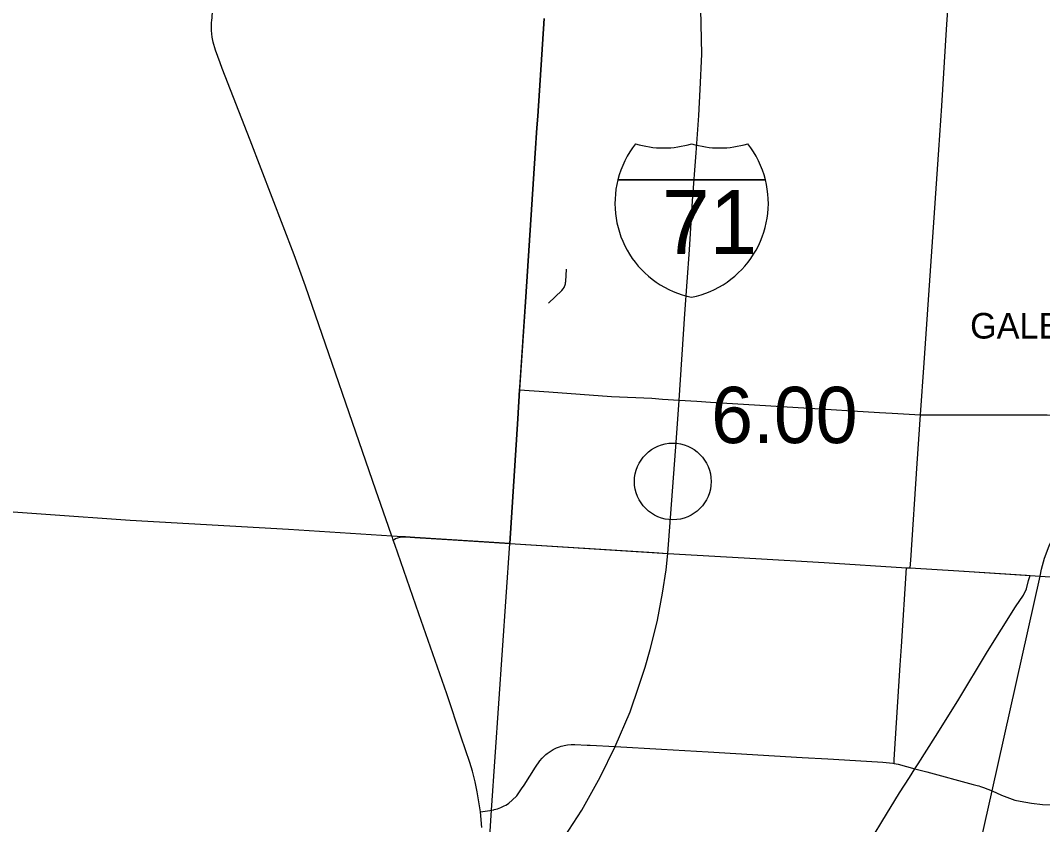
# Model space of a CAD drawing. Extents: x 1597222 to 1925846, y 496284 to 911751.
# Drawn here: x 1835573 to 1855559, y 799690 to 815408 of the extents above; entities that cross this region are included whole.
import ezdxf

# ---------------------------------------------------------------- set-up
doc = ezdxf.new("R2010")
doc.units = 0
for name, color, linetype in [('Default', 7, 'Continuous'), ('GM_X_Corporation_Text', 7, 'Continuous'), ('GM_X_County_Road', 7, 'Continuous'), ('GM_X_Interstate_Route', 7, 'Continuous'), ('GM_X_Interstate_Shield', 7, 'Continuous'), ('GM_X_State_Route', 7, 'Continuous'), ('GM_X_Township', 7, 'Continuous'), ('GM_X_Township_Road', 7, 'Continuous')]:
    doc.layers.add(name, color=color, linetype=linetype)

msp = doc.modelspace()

# ---------------------------------------------------------------- linework, layer by layer
at = {"layer": 'Default'}
msp.add_circle((1848329, 806396), 750, dxfattribs=at)
at = {"layer": 'GM_X_County_Road'}
for points in [[(1852972, 804706), (1852981, 804856), (1853110, 806745), (1853175, 807697), (1853246, 808714), (1853530, 812876), (1853592, 813742), (1853681, 815234), (1853705, 815613), (1853731, 815995), (1853772, 816725), (1853832, 817646), (1853875, 818312), (1853892, 818538)], [(1842846, 805301), (1842837, 805328), (1842772, 805518), (1842519, 806229), (1841146, 810217), (1840928, 810827), (1840065, 813066), (1839518, 814468), (1839479, 814577), (1839387, 814825), (1839342, 814985), (1839324, 815084), (1839310, 815214), (1839307, 815315), (1839311, 815371), (1839312, 815408), (1839319, 815463), (1839325, 815513), (1839372, 815780)], [(1844595, 799631), (1844566, 799941), (1844505, 800330), (1844464, 800522), (1844412, 800732), (1844363, 800904), (1844193, 801395), (1843910, 802243), (1843360, 803811), (1842894, 805162), (1842863, 805251), (1842846, 805301)], [(1852657, 800886), (1852657, 800961), (1852774, 802805), (1852798, 803172), (1852898, 804710), (1852972, 804706)], [(1844838, 799981), (1844901, 799998), (1844968, 800023), (1845033, 800054), (1845064, 800071), (1845094, 800091), (1845124, 800110), (1845190, 800164), (1845278, 800253), (1845373, 800385), (1845425, 800462), (1845644, 800809), (1845729, 800932), (1845773, 800986), (1845847, 801059), (1845874, 801080), (1845931, 801120), (1845991, 801156), (1846052, 801187), (1846116, 801212), (1846148, 801222), (1846234, 801241), (1846270, 801248), (1846343, 801255), (1846416, 801256), (1846655, 801244)], [(1846655, 801244), (1846713, 801241), (1847205, 801213), (1848107, 801161), (1849018, 801108), (1850858, 801002), (1851359, 800976), (1852118, 800926), (1852433, 800906), (1852629, 800889), (1852657, 800886), (1852736, 800868), (1853063, 800779), (1853297, 800719), (1854203, 800475), (1854282, 800454), (1854310, 800445)], [(1851239, 797854), (1851501, 798281), (1851653, 798524), (1851853, 798834), (1852115, 799249), (1852419, 799742), (1852763, 800311), (1852954, 800610), (1853063, 800779)], [(1854310, 800445), (1854348, 800433), (1854402, 800414), (1854573, 800349)], [(1854573, 800349), (1854755, 800266), (1854914, 800205), (1855015, 800169), (1855118, 800145), (1855340, 800109), (1855555, 800083), (1855746, 800073), (1856041, 800054), (1856308, 800043), (1856579, 800027), (1856677, 800021), (1856906, 800027), (1857196, 800056), (1857340, 800059), (1857473, 800073), (1857580, 800087), (1857682, 800095), (1857756, 800098), (1857798, 800096), (1857874, 800083), (1857988, 800064)], [(1844566, 799941), (1844753, 799964), (1844785, 799970), (1844828, 799978), (1844838, 799981)]]:
    msp.add_lwpolyline(points, dxfattribs=at)
at = {"layer": 'GM_X_Interstate_Route'}
msp.add_lwpolyline([(1846211, 799449), (1846552, 799972), (1846911, 800613), (1847205, 801213), (1847493, 801891), (1847666, 802395), (1847786, 802765), (1847888, 803110), (1847964, 803419), (1848028, 803685), (1848125, 804211), (1848200, 804670), (1848231, 804991), (1848401, 807248), (1848453, 807987), (1848565, 809674), (1848656, 810925), (1848716, 811884), (1848786, 812818), (1848839, 813548), (1848865, 814059), (1848894, 814749), (1848860, 816509)], dxfattribs=at)
at = {"layer": 'GM_X_Interstate_Shield'}
for p, q in [((1847254, 812294), (1850140, 812294)), ((1850140, 812294), (1847254, 812294)), ((1850140, 812294), (1847254, 812294)), ((1847254, 812294), (1850140, 812294)), ((1850140, 812294), (1847254, 812294)), ((1850140, 812294), (1847254, 812294))]:
    msp.add_line(p, q, dxfattribs=at)
for centre, start, end in [((1849072, 811835), 141.669, 165.8066), ((1849072, 811835), 141.669, 165.8066), ((1848149, 814791), 253.0091, 286.9909), ((1848149, 814791), 253.0091, 286.9909), ((1849245, 814791), 253.0091, 286.9909), ((1849245, 814791), 253.0091, 286.9909), ((1848322, 811835), 14.1934, 38.331), ((1848322, 811835), 14.1934, 38.331), ((1849072, 811835), 165.8066, 258.463), ((1849072, 811835), 165.8066, 258.463), ((1848322, 811835), 281.537, 14.1934), ((1848322, 811835), 281.537, 14.1934)]:
    msp.add_arc(centre, 1875, start, end, dxfattribs=at)
at = {"layer": 'GM_X_State_Route'}
msp.add_lwpolyline([(1853225, 794338), (1854573, 800349), (1855512, 804546), (1855541, 804679), (1855596, 804898), (1855689, 805139), (1855836, 805465), (1855908, 805599), (1856008, 805767), (1856148, 805978), (1856255, 806119), (1856504, 806413), (1857597, 807668), (1858467, 808668), (1858818, 809072), (1859440, 809788), (1860025, 810459)], dxfattribs=at)
at = {"layer": 'GM_X_Township'}
for points in [[(1845813, 815443), (1845687, 813540), (1845670, 813309), (1845637, 812811), (1845452, 810003), (1845333, 808188), (1845296, 807619), (1845145, 805182), (1843287, 805303), (1843103, 805315), (1843041, 805313), (1842837, 805328), (1840812, 805456), (1837716, 805633), (1832763, 805986)], [(1844685, 798421), (1844785, 799970), (1845145, 805182), (1848231, 804991), (1849953, 804892), (1851286, 804810), (1852898, 804710), (1852972, 804706), (1853920, 804647), (1855314, 804559), (1855512, 804546), (1855904, 804520)]]:
    msp.add_lwpolyline(points, dxfattribs=at)
at = {"layer": 'GM_X_Township_Road'}
for points in [[(1845336, 808240), (1845452, 810003), (1845637, 812811), (1845670, 813309), (1845687, 813540), (1845813, 815443)], [(1845901, 809883), (1846157, 810131), (1846187, 810162), (1846202, 810185), (1846214, 810206), (1846226, 810238), (1846229, 810261), (1846233, 810284), (1846236, 810308), (1846248, 810548)], [(1845145, 805182), (1845296, 807619), (1845333, 808188), (1845336, 808240)], [(1845333, 808188), (1845902, 808151), (1847128, 808058), (1847922, 808022), (1848130, 808008), (1848453, 807987), (1848798, 807964), (1849069, 807946), (1851423, 807800), (1851838, 807775), (1852372, 807742), (1852621, 807728), (1853175, 807697)], [(1853175, 807697), (1854218, 807699), (1855651, 807697), (1856991, 807682), (1857244, 807678), (1857423, 807675), (1857597, 807668)], [(1842863, 805251), (1842909, 805278), (1842951, 805293), (1842996, 805306), (1843041, 805313), (1843065, 805314)], [(1843065, 805314), (1843103, 805315), (1843287, 805303), (1844132, 805248)], [(1844132, 805248), (1845145, 805182)], [(1845145, 805182), (1847965, 805008)], [(1847965, 805008), (1848231, 804991), (1849953, 804892), (1851286, 804810), (1852898, 804710)], [(1852972, 804706), (1853920, 804647), (1855248, 804563)], [(1853063, 800779), (1853085, 800818), (1853124, 800877), (1853467, 801413), (1853904, 802110), (1854482, 803071), (1855027, 803947), (1855187, 804174), (1855245, 804296), (1855285, 804458), (1855314, 804559)], [(1855248, 804563), (1855314, 804559), (1855512, 804546)], [(1855512, 804546), (1855904, 804520), (1856177, 804502), (1856300, 804491), (1856579, 804475), (1858107, 804378)]]:
    msp.add_lwpolyline(points, dxfattribs=at)

# ---------------------------------------------------------------- texts
at = {"layer": 'Default'}
msp.add_text('6.00', height=1100, dxfattribs=at).set_placement((1849079, 807146))
at = {"layer": 'GM_X_Corporation_Text'}
msp.add_text('GALENA', height=500, rotation=0, dxfattribs=at).set_placement((1854142, 809190))
at = {"layer": 'GM_X_Interstate_Shield'}
msp.add_text('71', height=1250, dxfattribs=at).set_placement((1848119, 810841))
msp.add_text('71', height=1250, dxfattribs=at).set_placement((1848119, 810841))

doc.saveas('drawing.dxf')
